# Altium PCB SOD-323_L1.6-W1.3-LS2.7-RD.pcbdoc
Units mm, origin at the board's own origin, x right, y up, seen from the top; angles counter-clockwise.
Board outline 16.2 x 14.73 mm, 2 copper layers (Top Layer, Bottom Layer), stack 0 mm thick; 1 components, 0 nets, 2 pads, 0 vias.
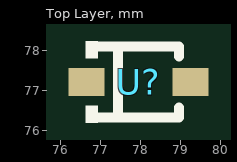
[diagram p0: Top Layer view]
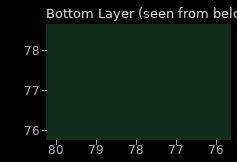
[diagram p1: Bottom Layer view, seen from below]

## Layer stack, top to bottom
Top Layer: signal copper (thickness not stored)
Bottom Layer: signal copper (thickness not stored)

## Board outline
86.05,69.85 69.85,69.85 69.85,84.582 86.05,84.582

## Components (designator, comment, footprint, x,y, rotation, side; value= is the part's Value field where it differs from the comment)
U? "" SOD-323_L1.6-W1.3-LS2.7-RD 77.95,77.216 r0 top

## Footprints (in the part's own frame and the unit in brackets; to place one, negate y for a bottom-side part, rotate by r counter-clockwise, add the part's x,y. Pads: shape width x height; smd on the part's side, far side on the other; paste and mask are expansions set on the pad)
SOD-323_L1.6-W1.3-LS2.7-RD [mm]
  rect 0.9x0.7 smd paste+0 mask+0.05: 1(-1.3,0) 2(1.3,0)
  silkscreen extent -1.32,-1.02 1.02,1.02

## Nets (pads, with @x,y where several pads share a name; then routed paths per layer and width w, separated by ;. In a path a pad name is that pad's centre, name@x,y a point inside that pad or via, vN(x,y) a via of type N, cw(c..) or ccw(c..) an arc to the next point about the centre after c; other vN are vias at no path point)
pads on no net: U?.1 U?.2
